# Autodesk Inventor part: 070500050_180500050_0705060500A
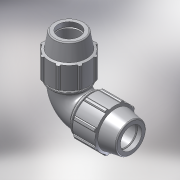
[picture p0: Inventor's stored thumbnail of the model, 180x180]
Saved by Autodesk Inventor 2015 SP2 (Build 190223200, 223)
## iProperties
Created: 2017-02
Part Number: 070500050_180500050_0705060500A
Material: PVC-Piping
Description: PLASSON 90° ELBOW 50-50
Document SubType Name: Modeling
Designer: KIM
Mass: 92.6774 g
Surface Area: 199.44 cm^2
Volume: 66.1981 cm^3
Density: 1.4 g/cm^3
Appearance: Smooth - White
Author: KIM
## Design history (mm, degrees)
derived "07050.ipt"
feature "Solid1::07050.ipt"
tag "TaggingFeature1"
body "Solid1"
other parameters: "d4" = 10.58333, "d5" = 31.75, "d7" = 96, "d9" = 18.14286, "d11" = 4.23333, "d13" = 120 deg, "d15" = 10 deg, "d16" = 83.52, "d18" = 2.5, "d19" = 35 deg, "d20" = 17.5 deg, "d21" = 89.28, "d23" = 0, "d25" = 360 deg, "d27" = 1.92, "d33" = 1, "d42" = 46.99, "d43" = 2.88, "d46" = 1.5, "d51" = 127, "d59" = 90 deg, "d63" = 93, "d64" = 45, "d67" = 72, "d68" = 2.11667, "d70" = 90 deg, "d71" = 7.5, "E_" = 96, "A_" = 127, "l_" = 93
